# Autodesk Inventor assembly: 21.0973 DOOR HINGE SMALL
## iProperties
Created: 2010-07
Part Number: 21.0973 DOOR HINGE SMALL
Document SubType Name: Assembly
Designer: Administrator
Author: Administrator
